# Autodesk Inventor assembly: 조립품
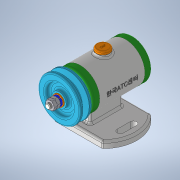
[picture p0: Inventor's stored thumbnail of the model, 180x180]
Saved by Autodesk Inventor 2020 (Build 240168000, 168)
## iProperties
Created: 2021-09
Part Number: 조립품
Document SubType Name: Assembly
Designer: Administrator
Author: Administrator
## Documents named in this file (14)
- C:\Users\Administrator\Desktop\710906V1016\조립품.iam
- C:\Users\Administrator\Desktop\710906V1016\본체.ipt
- C:\Users\Administrator\Desktop\710906V1016\캡.ipt
- C:\Users\Administrator\Desktop\710906V1016\너트 M8.ipt
- C:\Users\Administrator\Desktop\710906V1016\앞커버.ipt
- C:\Users\Administrator\Desktop\710906V1016\뒤커버.ipt
- C:\Users\Administrator\Desktop\710906V1016\오일 실 15x25x7.ipt
- C:\Users\Administrator\Desktop\710906V1016\베어링 15x32x9.ipt
- C:\Users\Administrator\Desktop\710906V1016\V벨트풀리.ipt
- C:\Users\Administrator\Desktop\710906V1016\볼트 M4x12.ipt
- C:\Users\Administrator\Desktop\710906V1016\스프링와셔 8.ipt
- C:\Users\Administrator\Desktop\710906V1016\와셔 8x17.ipt
- C:\Users\Administrator\Desktop\710906V1016\축.ipt
- C:\Users\Administrator\Desktop\710906V1016\키 3x3.ipt
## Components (1 placed, 1 different names)
1. V벨트풀리:1 — 각도:2
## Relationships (1: Angle 1)
- 각도:2 [Angle]: V벨트풀리:1
